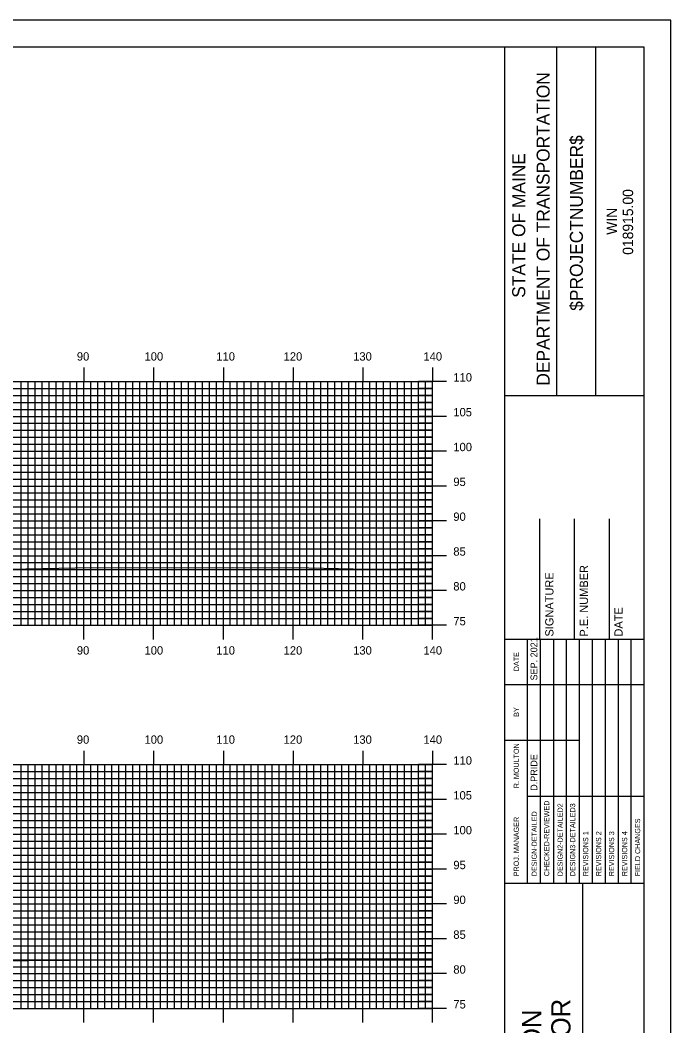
# Model space of a CAD drawing. Extents: x 1759430 to 1759773, y 442591 to 442811.
# Drawn here: x 1759676.5 to 1759769.9, y 442666.2 to 442810.5 of the extents above; entities that cross this region are included whole.
import ezdxf

# ---------------------------------------------------------------- set-up
doc = ezdxf.new("R2010")
doc.units = 0
for name, color, linetype in [('BORDER', 7, 'Continuous'), ('H_V ANNOTATION', 7, 'Continuous'), ('MAJOR', 7, 'Continuous'), ('MINOR', 7, 'Continuous'), ('PLOT BOUNDARY', 7, 'Continuous'), ('S_Roadway_Centerline', 7, 'Continuous')]:
    doc.layers.add(name, color=color, linetype=linetype)

msp = doc.modelspace()

# ---------------------------------------------------------------- linework, layer by layer
at = {"layer": 'BORDER'}
for p, q in [((1759746.07, 442596.67), (1759746.07, 442806.67)), ((1759753.53, 442756.66), (1759753.53, 442806.66)), ((1759759.12, 442756.66), (1759759.12, 442806.66)), ((1759746.08, 442756.65), (1759766.07, 442756.65)), ((1759751.07, 442721.67), (1759751.07, 442738.97)), ((1759756.07, 442721.67), (1759756.07, 442738.97)), ((1759761.07, 442721.67), (1759761.07, 442738.97)), ((1759746.07, 442721.67), (1759766.07, 442721.67)), ((1759746.07, 442686.67), (1759766.07, 442686.67)), ((1759757.26, 442616.67), (1759757.26, 442686.67))]:
    msp.add_line(p, q, dxfattribs=at)
msp.add_lwpolyline([(1759446.07, 442596.67), (1759766.07, 442596.67), (1759766.07, 442806.67), (1759446.07, 442806.67)], close=True, dxfattribs=at)
for points in [[(1759749.3, 442715.17), (1759749.3, 442721.67)], [(1759751.17, 442686.68), (1759751.17, 442721.67)], [(1759753.03, 442721.67), (1759753.03, 442686.68)], [(1759754.9, 442686.68), (1759754.9, 442721.67)], [(1759756.76, 442686.68), (1759756.76, 442721.67)], [(1759758.62, 442686.68), (1759758.62, 442721.67)], [(1759760.49, 442686.68), (1759760.49, 442721.67)], [(1759762.35, 442686.68), (1759762.35, 442721.67)], [(1759764.21, 442686.68), (1759764.21, 442721.67)], [(1759749.31, 442686.68), (1759749.31, 442720.26)], [(1759746.07, 442715.17), (1759766.07, 442715.17)], [(1759746.07, 442707.17), (1759749.31, 442707.17)], [(1759749.3, 442707.17), (1759756.76, 442707.17)], [(1759749.3, 442699.17), (1759766.07, 442699.17)]]:
    msp.add_lwpolyline(points, dxfattribs=at)
at = {"layer": 'MAJOR'}
for p, q in [((1759685.67, 442760.67), (1759685.67, 442758.67)), ((1759695.67, 442760.67), (1759695.67, 442758.67)), ((1759705.67, 442760.67), (1759705.67, 442758.67)), ((1759715.67, 442760.67), (1759715.67, 442758.67)), ((1759725.67, 442760.67), (1759725.67, 442758.67)), ((1759735.67, 442760.67), (1759735.67, 442758.67)), ((1759455.67, 442758.67), (1759735.67, 442758.67)), ((1759455.67, 442758.67), (1759735.67, 442758.67)), ((1759685.67, 442723.67), (1759685.67, 442758.67)), ((1759695.67, 442723.67), (1759695.67, 442758.67)), ((1759705.67, 442723.67), (1759705.67, 442758.67)), ((1759715.67, 442723.67), (1759715.67, 442758.67)), ((1759725.67, 442723.67), (1759725.67, 442758.67)), ((1759737.68, 442758.67), (1759733.67, 442758.67)), ((1759735.67, 442723.67), (1759735.67, 442758.67)), ((1759735.67, 442723.67), (1759735.67, 442758.67)), ((1759455.67, 442753.67), (1759735.67, 442753.67)), ((1759737.68, 442753.67), (1759733.67, 442753.67)), ((1759455.67, 442748.67), (1759735.67, 442748.67)), ((1759737.68, 442748.67), (1759733.67, 442748.67)), ((1759455.67, 442743.67), (1759735.67, 442743.67)), ((1759737.68, 442743.67), (1759733.67, 442743.67)), ((1759455.67, 442738.67), (1759735.67, 442738.67)), ((1759737.68, 442738.67), (1759733.67, 442738.67)), ((1759455.67, 442733.67), (1759735.67, 442733.67)), ((1759737.68, 442733.67), (1759733.67, 442733.67)), ((1759455.67, 442728.67), (1759735.67, 442728.67)), ((1759737.68, 442728.67), (1759733.67, 442728.67)), ((1759455.67, 442723.67), (1759735.67, 442723.67)), ((1759455.67, 442723.67), (1759735.67, 442723.67)), ((1759685.67, 442721.66), (1759685.67, 442723.67)), ((1759695.67, 442721.66), (1759695.67, 442723.67)), ((1759705.67, 442721.66), (1759705.67, 442723.67)), ((1759715.67, 442721.66), (1759715.67, 442723.67)), ((1759725.67, 442721.66), (1759725.67, 442723.67)), ((1759737.68, 442723.67), (1759733.67, 442723.67)), ((1759735.67, 442721.66), (1759735.67, 442723.67)), ((1759685.67, 442705.67), (1759685.67, 442703.67)), ((1759695.67, 442705.67), (1759695.67, 442703.67)), ((1759705.67, 442705.67), (1759705.67, 442703.67)), ((1759715.67, 442705.67), (1759715.67, 442703.67)), ((1759725.67, 442705.67), (1759725.67, 442703.67)), ((1759735.67, 442705.67), (1759735.67, 442703.67)), ((1759455.67, 442703.67), (1759735.67, 442703.67)), ((1759455.67, 442703.67), (1759735.67, 442703.67)), ((1759685.67, 442668.67), (1759685.67, 442703.67)), ((1759695.67, 442668.67), (1759695.67, 442703.67)), ((1759705.67, 442668.67), (1759705.67, 442703.67)), ((1759715.67, 442668.67), (1759715.67, 442703.67)), ((1759725.67, 442668.67), (1759725.67, 442703.67)), ((1759737.68, 442703.67), (1759733.67, 442703.67)), ((1759735.67, 442668.67), (1759735.67, 442703.67)), ((1759735.67, 442668.67), (1759735.67, 442703.67)), ((1759455.67, 442698.67), (1759735.67, 442698.67)), ((1759737.68, 442698.67), (1759733.67, 442698.67)), ((1759455.67, 442693.67), (1759735.67, 442693.67)), ((1759737.68, 442693.67), (1759733.67, 442693.67)), ((1759455.67, 442688.67), (1759735.67, 442688.67)), ((1759737.68, 442688.67), (1759733.67, 442688.67)), ((1759455.67, 442683.67), (1759735.67, 442683.67)), ((1759737.68, 442683.67), (1759733.67, 442683.67)), ((1759455.67, 442678.67), (1759735.67, 442678.67)), ((1759737.68, 442678.67), (1759733.67, 442678.67)), ((1759455.67, 442673.67), (1759735.67, 442673.67)), ((1759737.68, 442673.67), (1759733.67, 442673.67)), ((1759455.67, 442668.67), (1759735.67, 442668.67)), ((1759455.67, 442668.67), (1759735.67, 442668.67)), ((1759685.67, 442666.66), (1759685.67, 442668.67)), ((1759695.67, 442666.66), (1759695.67, 442668.67)), ((1759705.67, 442666.66), (1759705.67, 442668.67)), ((1759715.67, 442666.66), (1759715.67, 442668.67)), ((1759725.67, 442666.66), (1759725.67, 442668.67)), ((1759737.68, 442668.67), (1759733.67, 442668.67)), ((1759735.67, 442666.66), (1759735.67, 442668.67))]:
    msp.add_line(p, q, dxfattribs=at)
at = {"layer": 'MINOR'}
for p, q in [((1759676.67, 442723.67), (1759676.67, 442758.67)), ((1759677.67, 442723.67), (1759677.67, 442758.67)), ((1759678.67, 442723.67), (1759678.67, 442758.67)), ((1759679.67, 442723.67), (1759679.67, 442758.67)), ((1759680.67, 442723.67), (1759680.67, 442758.67)), ((1759681.67, 442723.67), (1759681.67, 442758.67)), ((1759682.67, 442723.67), (1759682.67, 442758.67)), ((1759683.67, 442723.67), (1759683.67, 442758.67)), ((1759684.67, 442723.67), (1759684.67, 442758.67)), ((1759686.67, 442723.67), (1759686.67, 442758.67)), ((1759687.67, 442723.67), (1759687.67, 442758.67)), ((1759688.67, 442723.67), (1759688.67, 442758.67)), ((1759689.67, 442723.67), (1759689.67, 442758.67)), ((1759690.67, 442723.67), (1759690.67, 442758.67)), ((1759691.67, 442723.67), (1759691.67, 442758.67)), ((1759692.67, 442723.67), (1759692.67, 442758.67)), ((1759693.67, 442723.67), (1759693.67, 442758.67)), ((1759694.67, 442723.67), (1759694.67, 442758.67)), ((1759696.67, 442723.67), (1759696.67, 442758.67)), ((1759697.67, 442723.67), (1759697.67, 442758.67)), ((1759698.67, 442723.67), (1759698.67, 442758.67)), ((1759699.67, 442723.67), (1759699.67, 442758.67)), ((1759700.67, 442723.67), (1759700.67, 442758.67)), ((1759701.67, 442723.67), (1759701.67, 442758.67)), ((1759702.67, 442723.67), (1759702.67, 442758.67)), ((1759703.67, 442723.67), (1759703.67, 442758.67)), ((1759704.67, 442723.67), (1759704.67, 442758.67)), ((1759706.67, 442723.67), (1759706.67, 442758.67)), ((1759707.67, 442723.67), (1759707.67, 442758.67)), ((1759708.67, 442723.67), (1759708.67, 442758.67)), ((1759709.67, 442723.67), (1759709.67, 442758.67)), ((1759710.67, 442723.67), (1759710.67, 442758.67)), ((1759711.67, 442723.67), (1759711.67, 442758.67)), ((1759712.67, 442723.67), (1759712.67, 442758.67)), ((1759713.67, 442723.67), (1759713.67, 442758.67)), ((1759714.67, 442723.67), (1759714.67, 442758.67)), ((1759716.67, 442723.67), (1759716.67, 442758.67)), ((1759717.67, 442723.67), (1759717.67, 442758.67)), ((1759718.67, 442723.67), (1759718.67, 442758.67)), ((1759719.67, 442723.67), (1759719.67, 442758.67)), ((1759720.67, 442723.67), (1759720.67, 442758.67)), ((1759721.67, 442723.67), (1759721.67, 442758.67)), ((1759722.67, 442723.67), (1759722.67, 442758.67)), ((1759723.67, 442723.67), (1759723.67, 442758.67)), ((1759724.67, 442723.67), (1759724.67, 442758.67)), ((1759726.67, 442723.67), (1759726.67, 442758.67)), ((1759727.67, 442723.67), (1759727.67, 442758.67)), ((1759728.67, 442723.67), (1759728.67, 442758.67)), ((1759729.67, 442723.67), (1759729.67, 442758.67)), ((1759730.67, 442723.67), (1759730.67, 442758.67)), ((1759731.67, 442723.67), (1759731.67, 442758.67)), ((1759732.67, 442723.67), (1759732.67, 442758.67)), ((1759733.67, 442723.67), (1759733.67, 442758.67)), ((1759734.67, 442723.67), (1759734.67, 442758.67)), ((1759455.67, 442757.67), (1759735.67, 442757.67)), ((1759735.67, 442757.67), (1759733.67, 442757.67)), ((1759455.67, 442756.67), (1759735.67, 442756.67)), ((1759455.67, 442755.67), (1759735.67, 442755.67)), ((1759735.67, 442756.67), (1759733.67, 442756.67)), ((1759735.67, 442755.67), (1759733.67, 442755.67)), ((1759455.67, 442754.67), (1759735.67, 442754.67)), ((1759735.67, 442754.67), (1759733.67, 442754.67)), ((1759455.67, 442752.67), (1759735.67, 442752.67)), ((1759455.67, 442751.67), (1759735.67, 442751.67)), ((1759735.67, 442752.67), (1759733.67, 442752.67)), ((1759735.67, 442751.67), (1759733.67, 442751.67)), ((1759455.67, 442750.67), (1759735.67, 442750.67)), ((1759735.67, 442750.67), (1759733.67, 442750.67)), ((1759455.67, 442749.67), (1759735.67, 442749.67)), ((1759735.67, 442749.67), (1759733.67, 442749.67)), ((1759455.67, 442747.67), (1759735.67, 442747.67)), ((1759735.67, 442747.67), (1759733.67, 442747.67)), ((1759455.67, 442746.67), (1759735.67, 442746.67)), ((1759455.67, 442745.67), (1759735.67, 442745.67)), ((1759735.67, 442746.67), (1759733.67, 442746.67)), ((1759735.67, 442745.67), (1759733.67, 442745.67)), ((1759455.67, 442744.67), (1759735.67, 442744.67)), ((1759735.67, 442744.67), (1759733.67, 442744.67)), ((1759455.67, 442742.67), (1759735.67, 442742.67)), ((1759735.67, 442742.67), (1759733.67, 442742.67)), ((1759455.67, 442741.67), (1759735.67, 442741.67)), ((1759735.67, 442741.67), (1759733.67, 442741.67)), ((1759455.67, 442740.67), (1759735.67, 442740.67)), ((1759735.67, 442740.67), (1759733.67, 442740.67)), ((1759455.67, 442739.67), (1759735.67, 442739.67)), ((1759735.67, 442739.67), (1759733.67, 442739.67)), ((1759455.67, 442737.67), (1759735.67, 442737.67)), ((1759735.67, 442737.67), (1759733.67, 442737.67)), ((1759455.67, 442736.67), (1759735.67, 442736.67)), ((1759455.67, 442735.67), (1759735.67, 442735.67)), ((1759735.67, 442736.67), (1759733.67, 442736.67)), ((1759735.67, 442735.67), (1759733.67, 442735.67)), ((1759455.67, 442734.67), (1759735.67, 442734.67)), ((1759735.67, 442734.67), (1759733.67, 442734.67)), ((1759455.67, 442732.67), (1759735.67, 442732.67)), ((1759735.67, 442732.67), (1759733.67, 442732.67)), ((1759455.67, 442731.67), (1759735.67, 442731.67)), ((1759735.67, 442731.67), (1759733.67, 442731.67)), ((1759455.67, 442730.67), (1759735.67, 442730.67)), ((1759455.67, 442729.67), (1759735.67, 442729.67)), ((1759735.67, 442730.67), (1759733.67, 442730.67)), ((1759735.67, 442729.67), (1759733.67, 442729.67)), ((1759455.67, 442727.67), (1759735.67, 442727.67)), ((1759735.67, 442727.67), (1759733.67, 442727.67)), ((1759455.67, 442726.67), (1759735.67, 442726.67)), ((1759455.67, 442725.67), (1759735.67, 442725.67)), ((1759735.67, 442726.67), (1759733.67, 442726.67)), ((1759735.67, 442725.67), (1759733.67, 442725.67)), ((1759455.67, 442724.67), (1759735.67, 442724.67)), ((1759735.67, 442724.67), (1759733.67, 442724.67)), ((1759676.67, 442668.67), (1759676.67, 442703.67)), ((1759677.67, 442668.67), (1759677.67, 442703.67)), ((1759678.67, 442668.67), (1759678.67, 442703.67)), ((1759679.67, 442668.67), (1759679.67, 442703.67)), ((1759680.67, 442668.67), (1759680.67, 442703.67)), ((1759681.67, 442668.67), (1759681.67, 442703.67)), ((1759682.67, 442668.67), (1759682.67, 442703.67)), ((1759683.67, 442668.67), (1759683.67, 442703.67)), ((1759684.67, 442668.67), (1759684.67, 442703.67)), ((1759686.67, 442668.67), (1759686.67, 442703.67)), ((1759687.67, 442668.67), (1759687.67, 442703.67)), ((1759688.67, 442668.67), (1759688.67, 442703.67)), ((1759689.67, 442668.67), (1759689.67, 442703.67)), ((1759690.67, 442668.67), (1759690.67, 442703.67)), ((1759691.67, 442668.67), (1759691.67, 442703.67)), ((1759692.67, 442668.67), (1759692.67, 442703.67)), ((1759693.67, 442668.67), (1759693.67, 442703.67)), ((1759694.67, 442668.67), (1759694.67, 442703.67)), ((1759696.67, 442668.67), (1759696.67, 442703.67)), ((1759697.67, 442668.67), (1759697.67, 442703.67)), ((1759698.67, 442668.67), (1759698.67, 442703.67)), ((1759699.67, 442668.67), (1759699.67, 442703.67)), ((1759700.67, 442668.67), (1759700.67, 442703.67)), ((1759701.67, 442668.67), (1759701.67, 442703.67)), ((1759702.67, 442668.67), (1759702.67, 442703.67)), ((1759703.67, 442668.67), (1759703.67, 442703.67)), ((1759704.67, 442668.67), (1759704.67, 442703.67)), ((1759706.67, 442668.67), (1759706.67, 442703.67)), ((1759707.67, 442668.67), (1759707.67, 442703.67)), ((1759708.67, 442668.67), (1759708.67, 442703.67)), ((1759709.67, 442668.67), (1759709.67, 442703.67)), ((1759710.67, 442668.67), (1759710.67, 442703.67)), ((1759711.67, 442668.67), (1759711.67, 442703.67)), ((1759712.67, 442668.67), (1759712.67, 442703.67)), ((1759713.67, 442668.67), (1759713.67, 442703.67)), ((1759714.67, 442668.67), (1759714.67, 442703.67)), ((1759716.67, 442668.67), (1759716.67, 442703.67)), ((1759717.67, 442668.67), (1759717.67, 442703.67)), ((1759718.67, 442668.67), (1759718.67, 442703.67)), ((1759719.67, 442668.67), (1759719.67, 442703.67)), ((1759720.67, 442668.67), (1759720.67, 442703.67)), ((1759721.67, 442668.67), (1759721.67, 442703.67)), ((1759722.67, 442668.67), (1759722.67, 442703.67)), ((1759723.67, 442668.67), (1759723.67, 442703.67)), ((1759724.67, 442668.67), (1759724.67, 442703.67)), ((1759726.67, 442668.67), (1759726.67, 442703.67)), ((1759727.67, 442668.67), (1759727.67, 442703.67)), ((1759728.67, 442668.67), (1759728.67, 442703.67)), ((1759729.67, 442668.67), (1759729.67, 442703.67)), ((1759730.67, 442668.67), (1759730.67, 442703.67)), ((1759731.67, 442668.67), (1759731.67, 442703.67)), ((1759732.67, 442668.67), (1759732.67, 442703.67)), ((1759733.67, 442668.67), (1759733.67, 442703.67)), ((1759734.67, 442668.67), (1759734.67, 442703.67)), ((1759455.67, 442702.67), (1759735.67, 442702.67)), ((1759735.67, 442702.67), (1759733.67, 442702.67)), ((1759455.67, 442701.67), (1759735.67, 442701.67)), ((1759735.67, 442701.67), (1759733.67, 442701.67)), ((1759455.67, 442700.67), (1759735.67, 442700.67)), ((1759455.67, 442699.67), (1759735.67, 442699.67)), ((1759735.67, 442700.67), (1759733.67, 442700.67)), ((1759735.67, 442699.67), (1759733.67, 442699.67)), ((1759455.67, 442697.67), (1759735.67, 442697.67)), ((1759455.67, 442696.67), (1759735.67, 442696.67)), ((1759735.67, 442697.67), (1759733.67, 442697.67)), ((1759735.67, 442696.67), (1759733.67, 442696.67)), ((1759455.67, 442695.67), (1759735.67, 442695.67)), ((1759735.67, 442695.67), (1759733.67, 442695.67)), ((1759455.67, 442694.67), (1759735.67, 442694.67)), ((1759735.67, 442694.67), (1759733.67, 442694.67)), ((1759455.67, 442692.67), (1759735.67, 442692.67)), ((1759735.67, 442692.67), (1759733.67, 442692.67)), ((1759455.67, 442691.67), (1759735.67, 442691.67)), ((1759455.67, 442690.67), (1759735.67, 442690.67)), ((1759735.67, 442691.67), (1759733.67, 442691.67)), ((1759735.67, 442690.67), (1759733.67, 442690.67)), ((1759455.67, 442689.67), (1759735.67, 442689.67)), ((1759735.67, 442689.67), (1759733.67, 442689.67)), ((1759455.67, 442687.67), (1759735.67, 442687.67)), ((1759455.67, 442686.67), (1759735.67, 442686.67)), ((1759735.67, 442687.67), (1759733.67, 442687.67)), ((1759735.67, 442686.67), (1759733.67, 442686.67)), ((1759455.67, 442685.67), (1759735.67, 442685.67)), ((1759735.67, 442685.67), (1759733.67, 442685.67)), ((1759455.67, 442684.67), (1759735.67, 442684.67)), ((1759735.67, 442684.67), (1759733.67, 442684.67)), ((1759455.67, 442682.67), (1759735.67, 442682.67)), ((1759735.67, 442682.67), (1759733.67, 442682.67)), ((1759455.67, 442681.67), (1759735.67, 442681.67)), ((1759455.67, 442680.67), (1759735.67, 442680.67)), ((1759735.67, 442681.67), (1759733.67, 442681.67)), ((1759735.67, 442680.67), (1759733.67, 442680.67)), ((1759455.67, 442679.67), (1759735.67, 442679.67)), ((1759735.67, 442679.67), (1759733.67, 442679.67)), ((1759455.67, 442677.67), (1759735.67, 442677.67)), ((1759735.67, 442677.67), (1759733.67, 442677.67)), ((1759455.67, 442676.67), (1759735.67, 442676.67)), ((1759735.67, 442676.67), (1759733.67, 442676.67)), ((1759455.67, 442675.67), (1759735.67, 442675.67)), ((1759735.67, 442675.67), (1759733.67, 442675.67)), ((1759455.67, 442674.67), (1759735.67, 442674.67)), ((1759735.67, 442674.67), (1759733.67, 442674.67)), ((1759455.67, 442672.67), (1759735.67, 442672.67)), ((1759735.67, 442672.67), (1759733.67, 442672.67)), ((1759455.67, 442671.67), (1759735.67, 442671.67)), ((1759455.67, 442670.67), (1759735.67, 442670.67)), ((1759735.67, 442671.67), (1759733.67, 442671.67)), ((1759735.67, 442670.67), (1759733.67, 442670.67)), ((1759455.67, 442669.67), (1759735.67, 442669.67)), ((1759735.67, 442669.67), (1759733.67, 442669.67))]:
    msp.add_line(p, q, dxfattribs=at)
at = {"layer": 'PLOT BOUNDARY'}
msp.add_lwpolyline([(1759429.89, 442590.55), (1759769.89, 442590.55), (1759769.89, 442810.55), (1759429.89, 442810.55)], close=True, dxfattribs=at)
at = {"layer": 'S_Roadway_Centerline'}
for points in [[(1759563.55, 442730.2), (1759581.08, 442730.58), (1759584.25, 442730.7), (1759594.89, 442730.87), (1759604.66, 442731.04), (1759606.49, 442731.06), (1759607.67, 442731.05), (1759618.28, 442730.91), (1759625.21, 442731.13), (1759629.63, 442731.24), (1759636.18, 442731.23), (1759645.83, 442731.29), (1759663.75, 442731.52), (1759666.9, 442731.56), (1759674.93, 442731.72), (1759686.82, 442731.98), (1759691.02, 442731.9), (1759706.99, 442731.98), (1759717.95, 442731.9), (1759726.46, 442731.74), (1759735.39, 442731.84), (1759735.67, 442731.84)], [(1759564.25, 442675.3), (1759567.34, 442675.32), (1759578.88, 442675.09), (1759592.48, 442675.26), (1759602.47, 442675.37), (1759608.85, 442675.39), (1759620.96, 442675.34), (1759628.82, 442675.37), (1759638.04, 442675.4), (1759648.72, 442675.56), (1759648.87, 442675.56), (1759660.89, 442675.39), (1759668.52, 442675.47), (1759677.56, 442675.58), (1759689.56, 442675.67), (1759704.69, 442675.71), (1759710.29, 442675.71), (1759720.18, 442675.79), (1759730.72, 442675.79), (1759734.55, 442675.78), (1759735.67, 442675.79)]]:
    msp.add_lwpolyline(points, dxfattribs=at)

# ---------------------------------------------------------------- texts
at = {"layer": 'BORDER'}
for s, height, p in [('DEPARTMENT OF TRANSPORTATION', 1.8635, (1759752.49, 442758.08)), ('$PROJECTNUMBER$', 1.8635, (1759757.26, 442768.82)), ('STATE OF MAINE', 1.8635, (1759748.99, 442770.69)), ('018915.00', 1.491, (1759764.47, 442776.86)), ('WIN', 1.491, (1759762.15, 442779.73)), ('SIGNATURE', 1.181, (1759753.04, 442722.06)), ('P.E. NUMBER', 1.1811, (1759758, 442722.06)), ('DATE', 1.181, (1759762.96, 442722.06)), ('SEP. 2021', 0.969, (1759750.72, 442715.76)), ('DATE', 0.743, (1759748.08, 442717.08)), ('BY', 0.743, (1759748.08, 442710.54)), ('R. MOULTON', 0.745, (1759748.08, 442700.28)), ('D.PRIDE', 0.969, (1759750.72, 442699.92)), ('CHECKED-REVIEWED', 0.7455, (1759752.44, 442687.65)), ('DESIGN-DETAILED', 0.7455, (1759750.65, 442687.65)), ('DESIGN2-DETAILED2', 0.7455, (1759754.37, 442687.65)), ('DESIGN3-DETAILED3', 0.7455, (1759756.16, 442687.65)), ('PROJ. MANAGER', 0.7455, (1759748.08, 442687.65)), ('FIELD CHANGES', 0.7455, (1759765.48, 442687.65)), ('REVISIONS 1', 0.7455, (1759758.03, 442687.65)), ('REVISIONS 2', 0.7455, (1759759.89, 442687.65)), ('REVISIONS 3', 0.7455, (1759761.75, 442687.65)), ('REVISIONS 4', 0.7455, (1759763.62, 442687.65)), ('1-395/ROUTE 9 CONNECTOR', 2.7557, (1759755.48, 442618.87)), ('BREWER TO EDDINGTON', 2.7557, (1759751.3, 442623.07))]:
    msp.add_text(s, height=height, rotation=90, dxfattribs=at).set_placement(p)
at = {"layer": 'H_V ANNOTATION'}
for s, p in [('90', (1759684.65, 442761.67)), ('100', (1759694.36, 442761.67)), ('110', (1759704.66, 442761.67)), ('120', (1759714.32, 442761.67)), ('130', (1759724.3, 442761.67)), ('140', (1759734.38, 442761.67)), ('110', (1759738.67, 442758.67)), ('105', (1759738.67, 442753.67)), ('100', (1759738.67, 442748.67)), ('95', (1759738.67, 442743.67)), ('90', (1759738.67, 442738.67)), ('85', (1759738.67, 442733.67)), ('80', (1759738.67, 442728.67)), ('75', (1759738.67, 442723.67)), ('90', (1759684.65, 442719.47)), ('100', (1759694.36, 442719.47)), ('110', (1759704.66, 442719.47)), ('120', (1759714.32, 442719.47)), ('130', (1759724.3, 442719.47)), ('140', (1759734.38, 442719.47)), ('90', (1759684.65, 442706.67)), ('100', (1759694.36, 442706.67)), ('110', (1759704.66, 442706.67)), ('120', (1759714.32, 442706.67)), ('130', (1759724.3, 442706.67)), ('140', (1759734.38, 442706.67)), ('110', (1759738.67, 442703.67)), ('105', (1759738.67, 442698.67)), ('100', (1759738.67, 442693.67)), ('95', (1759738.67, 442688.67)), ('90', (1759738.67, 442683.67)), ('85', (1759738.67, 442678.67)), ('80', (1759738.67, 442673.67)), ('75', (1759738.67, 442668.67))]:
    msp.add_text(s, height=1.2, dxfattribs=at).set_placement(p)

doc.saveas('drawing.dxf')
